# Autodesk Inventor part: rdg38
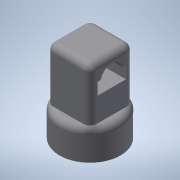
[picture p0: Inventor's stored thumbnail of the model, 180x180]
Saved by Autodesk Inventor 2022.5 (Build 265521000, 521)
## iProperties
Created: 2016-12
Part Number: rdg38
Material: 一般
Document SubType Name: Modeling
Designer: imaocorp
Density: 1 g/cm^3
Appearance: 既定
Author: imaocorp
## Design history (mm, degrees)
node "rdg38.x_t1"
node "rdg38"
node "Base1"
